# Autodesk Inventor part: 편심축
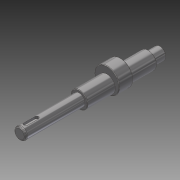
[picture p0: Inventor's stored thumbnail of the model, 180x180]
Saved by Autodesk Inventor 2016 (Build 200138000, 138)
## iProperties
Created: 2016-02
Part Number: 편심축
Material: 강철, 연강
Document SubType Name: Modeling
Designer: mduedu
Density: 1 g/cm^3
Appearance: 반광택
Author: mduedu
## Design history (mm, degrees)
sketch "스케치1"
  geometry: C1 r 6 at (0, 0); 1 further point
  constraints: 1 centre point, 1 coincident
  dimensions: "d0" = 12 diameter of C1
extrude "돌출1" new body sketch "스케치1" distance "d1" = 142; taper "d2" = 0 deg
chamfer "모따기1" distance "d3" = 0.5; stored, may be unused: second distance "d4" = 2, angle "d5" = 45 deg
node "작업 평면2"
sketch "스케치3"
  geometry: C1 r 8.5 at (0, 0); 1 further point
  constraints: 1 centre point, 1 coincident
  dimensions: "d12" = 17 diameter of C1
extrude "돌출3" join sketch "스케치3" distance "d13" = 70; taper "d14" = 0 deg
node "작업 평면3"
sketch "스케치4"
  geometry: L1 (0, 142)-(0, 0); L2 (-2, 136)-(-2, 125); L3 (2, 125)-(2, 136); L4 (6, 142)-(-6, 142) reference; A1 r 2 centre (0, 136) between (2, 136) and (-2, 136); A2 r 2 centre (0, 125) between (-2, 125) and (2, 125)
  constraints: 6 end point, 4 point on circle, 4 tangent, 2 centre point, 2 point on line, 1 midpoint, 1 parallel
  dimensions: "d15" = 4 distance between parallel lines of L2 L3; "d18" = 15 dimension on A2 A1; "d36" = 4 distance edge to line of A1 L4
extrude "돌출4" cut sketch "스케치4" distance "d19" = 2.5; taper "d20" = 0 deg
node "작업 평면1"
sketch "스케치2"
  geometry: C1 r 12.5 at (0, 3); C2 r 8.5 at (0, 0) reference; 1 further point
  constraints: 1 centre point, 1 vertical alignment
  dimensions: "d7" = 25 diameter of C1; "d32" = 3 distance of C1.centre point (0, 0)
extrude "돌출2" join sketch "스케치2" stored distance "d8" = 14; taper "d9" = 0 deg
sketch "스케치5"
  geometry: L1 (6, 82)-(6, 142) reference; L2 (-6, 82)-(-6, 142) reference; L3 (6, 115)-(-6, 115); L4 (6, 116.5)-(4.5, 115); L5 (6, 116.5)-(6, 115); L6 (4.5, 115)-(6, 115); L7 (6, 142)-(-6, 142) reference; 1 further point
  constraints: 8 end point, 4 point on line, 2 collinear, 1 perpendicular
  dimensions: "d22" = 3 diameter of L4.start L3; "d24" = 45 deg angle of L3 L4; "d37" = 27 distance between parallel lines of L7 L3
revolve "회전1" sketch "스케치5" stored, may be unused: angle "d25" = 90 deg
sketch "스케치6"
  geometry: L1 (6, 116.5)-(4.5, 115) reference; L2 (6, 113.5)-(4.5, 115) reference; 2 further points
  constraints: 1 coincident
node "작업 평면4"
chamfer "모따기2" distance "d33" = 0.5; stored, may be unused: second distance "d34" = 2, angle "d35" = 45 deg
sketch "스케치8"
  geometry: L1 (5.1, 142)-(6, 140.441); L2 (6, 82)-(6, 142) reference; L3 (6, 142)-(-6, 142) reference; L4 (0, 142)-(0, 86.696); 1 further point
  constraints: 4 end point, 2 point on line, 1 midpoint, 1 perpendicular
  dimensions: "d38" = 10.2 diameter of L1.start L4; "d43" = 30 deg angle of L2 L1
revolve "회전2" sketch "스케치8" stored, may be unused: angle "d45" = 90 deg
fillet "모깎기1" dims "d46" = 2, "d47" = 1
node "솔리드1"
other parameters: "d6" = -47, "d11" = -12, "d26" = 28
